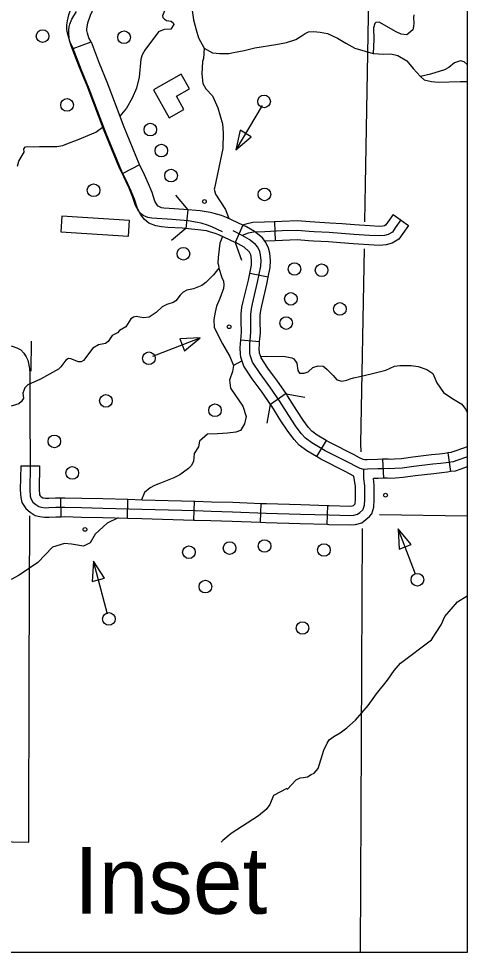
# Model space of a CAD drawing. Extents: x 1382482 to 1385815, y 1168351 to 1170484.
# Drawn here: x 1384797.7 to 1384939.9, y 1168702.4 to 1168998.2 of the extents above; entities that cross this region are included whole.
import ezdxf

# ---------------------------------------------------------------- set-up
doc = ezdxf.new("R2010")
doc.units = 0
for name, color, linetype in [('32', 7, 'Continuous'), ('35', 7, 'Continuous'), ('38', 7, 'Continuous'), ('45', 7, 'Continuous'), ('5', 7, 'Continuous'), ('57', 7, 'Continuous'), ('6', 7, 'Continuous'), ('Default', 7, 'Continuous'), ('R_No Plot', 7, 'Continuous')]:
    doc.layers.add(name, color=color, linetype=linetype)

msp = doc.modelspace()

# ---------------------------------------------------------------- linework, layer by layer
at = {"layer": '32'}
for p, q in [((1384876.81, 1168916.28), (1384870.93, 1168917.47)), ((1384874.06, 1168895.8), (1384868.08, 1168896.31)), ((1384882.46, 1168879.36), (1384877.53, 1168875.94)), ((1384895.17, 1168864.55), (1384892.09, 1168859.4)), ((1384913.04, 1168858.57), (1384913.3, 1168852.57)), ((1384933.73, 1168860.59), (1384934.57, 1168854.65)), ((1384798.36, 1168856.54), (1384804.35, 1168856.44)), ((1384811.16, 1168840.37), (1384811.08, 1168846.37)), ((1384832.15, 1168839.89), (1384832.32, 1168845.89)), ((1384853.26, 1168839.29), (1384853.43, 1168845.29)), ((1384874.33, 1168838.61), (1384874.57, 1168844.6)), ((1384895.47, 1168837.96), (1384895.65, 1168843.96))]:
    msp.add_line(p, q, dxfattribs=at)
for points in [[(1384876.81, 1168916.28), (1384877.44, 1168919.37), (1384877.54, 1168921.58), (1384877.33, 1168923.92), (1384876.9, 1168925.45), (1384876.04, 1168927.3), (1384874.93, 1168928.74), (1384872.96, 1168930.36), (1384872.42, 1168930.76), (1384869.95, 1168932.16), (1384868.74, 1168932.75)], [(1384939.88, 1168859.32), (1384939.35, 1168859.13), (1384936.85, 1168858.24), (1384935.35, 1168857.79), (1384933.16, 1168857.48), (1384931.42, 1168857.25), (1384928.9, 1168856.98), (1384922.98, 1168856.28), (1384919.28, 1168855.75), (1384916.95, 1168855.62), (1384915.36, 1168855.52), (1384914.76, 1168855.6), (1384913.4, 1168855.58), (1384911.48, 1168855.5), (1384908.27, 1168855.39), (1384907.11, 1168855.35), (1384905.93, 1168855.62), (1384904.41, 1168856.34), (1384902.61, 1168857.31), (1384894.87, 1168861.24), (1384890.66, 1168863.76), (1384888.63, 1168865.24), (1384887.27, 1168866.77), (1384885.41, 1168869.21), (1384883.31, 1168872.39), (1384880.4, 1168877.08), (1384877.3, 1168881.54), (1384874.2, 1168885.75), (1384871.81, 1168889.38), (1384871.48, 1168890.33), (1384871.03, 1168891.57), (1384870.98, 1168892.15), (1384870.94, 1168893.72), (1384870.98, 1168895.08), (1384871.29, 1168898.7), (1384871.23, 1168902.34), (1384871.23, 1168904.4), (1384871.44, 1168906.25), (1384871.81, 1168907.86), (1384873.42, 1168914.66), (1384874.45, 1168919.74), (1384874.54, 1168921.52), (1384874.37, 1168923.37), (1384874.08, 1168924.41), (1384873.46, 1168925.73), (1384872.76, 1168926.64), (1384871.11, 1168928), (1384870.78, 1168928.25), (1384868.56, 1168929.5), (1384865.7, 1168930.9)], [(1384870.93, 1168917.47), (1384871.47, 1168920.11), (1384871.53, 1168921.45), (1384871.41, 1168922.83), (1384871.26, 1168923.36), (1384870.89, 1168924.16), (1384870.59, 1168924.54), (1384869.25, 1168925.64), (1384869.13, 1168925.73), (1384866.33, 1168927.32)], [(1384868.08, 1168896.31), (1384868.29, 1168898.8), (1384868.23, 1168902.31), (1384868.23, 1168904.57), (1384868.47, 1168906.75), (1384868.89, 1168908.54), (1384870.49, 1168915.3), (1384870.93, 1168917.47)], [(1384874.06, 1168895.8), (1384874.3, 1168898.59), (1384874.23, 1168902.37), (1384874.23, 1168904.24), (1384874.4, 1168905.75), (1384874.73, 1168907.18), (1384876.35, 1168914.01), (1384876.81, 1168916.28)], [(1384877.53, 1168875.94), (1384874.86, 1168879.79), (1384871.74, 1168884.03), (1384869.1, 1168888.05), (1384868.65, 1168889.32), (1384868.06, 1168890.94), (1384867.99, 1168892), (1384867.94, 1168893.73), (1384867.99, 1168895.26), (1384868.08, 1168896.31)], [(1384882.46, 1168879.36), (1384879.74, 1168883.28), (1384876.67, 1168887.46), (1384874.52, 1168890.72), (1384874.31, 1168891.34), (1384873.99, 1168892.21), (1384873.98, 1168892.3), (1384873.94, 1168893.71), (1384873.98, 1168894.91), (1384874.06, 1168895.8)], [(1384895.17, 1168864.55), (1384892.32, 1168866.26), (1384890.66, 1168867.48), (1384889.59, 1168868.68), (1384887.86, 1168870.95), (1384885.83, 1168874.01), (1384882.91, 1168878.72), (1384882.46, 1168879.36)], [(1384892.09, 1168859.4), (1384889, 1168861.26), (1384886.6, 1168863.01), (1384884.96, 1168864.86), (1384882.97, 1168867.47), (1384880.78, 1168870.77), (1384877.89, 1168875.43), (1384877.53, 1168875.94)], [(1384913.04, 1168858.57), (1384911.37, 1168858.5), (1384908.16, 1168858.39), (1384907.4, 1168858.36), (1384906.92, 1168858.47), (1384905.76, 1168859.02), (1384904, 1168859.97), (1384896.32, 1168863.87), (1384895.17, 1168864.55)], [(1384939.88, 1168862.51), (1384938.34, 1168861.96), (1384935.92, 1168861.09), (1384934.7, 1168860.73), (1384933.73, 1168860.59)], [(1384903.95, 1168853.18), (1384901.22, 1168854.66), (1384893.42, 1168858.61), (1384892.09, 1168859.4)], [(1384933.73, 1168860.59), (1384932.75, 1168860.45), (1384931.07, 1168860.23), (1384928.57, 1168859.97), (1384922.58, 1168859.26), (1384918.99, 1168858.73), (1384916.77, 1168858.62), (1384915.47, 1168858.53), (1384914.94, 1168858.6), (1384913.31, 1168858.58), (1384913.04, 1168858.57)], [(1384798.36, 1168856.54), (1384798.22, 1168848.88), (1384798.36, 1168846.44), (1384798.74, 1168844.92), (1384799.96, 1168842.96), (1384801.33, 1168841.83), (1384802.94, 1168840.78), (1384804.45, 1168840.44), (1384805.89, 1168840.22), (1384807.42, 1168840.27), (1384809.52, 1168840.35), (1384811.16, 1168840.37)], [(1384801.36, 1168856.49), (1384801.22, 1168848.94), (1384801.34, 1168846.89), (1384801.54, 1168846.1), (1384802.25, 1168844.96), (1384803.11, 1168844.25), (1384804.13, 1168843.58), (1384805, 1168843.39), (1384806.06, 1168843.23), (1384807.32, 1168843.27), (1384809.44, 1168843.35), (1384812.36, 1168843.39), (1384817.67, 1168843.27), (1384824.36, 1168843.11), (1384836.79, 1168842.76), (1384853.59, 1168842.29), (1384858.71, 1168842.13), (1384865.45, 1168841.97), (1384876.11, 1168841.54), (1384887.05, 1168841.22), (1384896.05, 1168840.95), (1384902.83, 1168840.75), (1384903.9, 1168840.87), (1384905.11, 1168841.18), (1384905.82, 1168841.74), (1384906.73, 1168842.56), (1384906.92, 1168842.8), (1384907.32, 1168843.98), (1384907.4, 1168845.79), (1384907.4, 1168848.31), (1384907.4, 1168850.16), (1384907.08, 1168852.44), (1384907.08, 1168853.86), (1384907.11, 1168855.35)], [(1384804.35, 1168856.44), (1384804.22, 1168849), (1384804.32, 1168847.34), (1384804.33, 1168847.29), (1384804.53, 1168846.97), (1384804.89, 1168846.68), (1384805.32, 1168846.39), (1384805.55, 1168846.34), (1384806.24, 1168846.24), (1384807.22, 1168846.27), (1384809.37, 1168846.35), (1384811.08, 1168846.37)], [(1384939.88, 1168856.14), (1384937.79, 1168855.39), (1384935.99, 1168854.85), (1384934.57, 1168854.65)], [(1384895.65, 1168843.96), (1384896.14, 1168843.95), (1384902.71, 1168843.76), (1384903.35, 1168843.83), (1384903.76, 1168843.93), (1384903.89, 1168844.03), (1384904.3, 1168844.41), (1384904.34, 1168844.53), (1384904.4, 1168845.85), (1384904.4, 1168848.31), (1384904.4, 1168849.95), (1384903.95, 1168853.18)], [(1384913.3, 1168852.57), (1384911.59, 1168852.5), (1384910.11, 1168852.45)], [(1384934.57, 1168854.65), (1384933.56, 1168854.51), (1384931.78, 1168854.27), (1384929.24, 1168854), (1384923.37, 1168853.31), (1384919.58, 1168852.76), (1384917.13, 1168852.63), (1384915.25, 1168852.5), (1384914.58, 1168852.6), (1384913.49, 1168852.58), (1384913.3, 1168852.57)], [(1384895.47, 1168837.96), (1384895.97, 1168837.95), (1384902.96, 1168837.75), (1384904.44, 1168837.91), (1384906.47, 1168838.43), (1384907.76, 1168839.44), (1384908.9, 1168840.48), (1384909.59, 1168841.31), (1384910.3, 1168843.43), (1384910.4, 1168845.72), (1384910.4, 1168848.31), (1384910.4, 1168850.36), (1384910.11, 1168852.45)], [(1384811.08, 1168846.37), (1384812.37, 1168846.39), (1384817.74, 1168846.27), (1384824.43, 1168846.11), (1384832.32, 1168845.89)], [(1384832.32, 1168845.89), (1384836.88, 1168845.76), (1384853.43, 1168845.29)], [(1384853.43, 1168845.29), (1384853.68, 1168845.28), (1384858.79, 1168845.13), (1384865.54, 1168844.97), (1384874.57, 1168844.6)], [(1384874.57, 1168844.6), (1384876.21, 1168844.54), (1384887.13, 1168844.22), (1384895.65, 1168843.96)], [(1384811.16, 1168840.37), (1384812.34, 1168840.39), (1384817.6, 1168840.27), (1384824.28, 1168840.11), (1384832.15, 1168839.89)], [(1384832.15, 1168839.89), (1384836.71, 1168839.76), (1384853.26, 1168839.29)], [(1384853.26, 1168839.29), (1384853.51, 1168839.29), (1384858.63, 1168839.13), (1384865.35, 1168838.97), (1384874.33, 1168838.61)], [(1384874.33, 1168838.61), (1384876, 1168838.54), (1384886.96, 1168838.22), (1384895.47, 1168837.96)]]:
    msp.add_lwpolyline(points, dxfattribs=at)
at = {"layer": '35'}
for points in [[(1384835.69, 1169026.55), (1384836.09, 1169023.36), (1384836.89, 1169020.7), (1384838.35, 1169018.45), (1384845.77, 1169011.14), (1384850.52, 1169007.38), (1384852.13, 1169004.43), (1384853.07, 1168997.75), (1384853.93, 1168994.6), (1384854.68, 1168992.12), (1384856.51, 1168988.77)], [(1384845.77, 1169011.14), (1384845.29, 1169006.66), (1384844.66, 1169003.27), (1384843.9, 1169000.69), (1384843.32, 1168999.09), (1384843.44, 1168998.57), (1384843.92, 1168997.98), (1384844.6, 1168997.62), (1384846.04, 1168997.39), (1384846.68, 1168996.88), (1384846.92, 1168996.32), (1384845.89, 1168994.87), (1384843.78, 1168994.78), (1384842.03, 1168994), (1384837.65, 1168988.18), (1384836.86, 1168986.73), (1384836.43, 1168985.33), (1384835.87, 1168979.68), (1384835, 1168976.14), (1384833.69, 1168973.02), (1384831.83, 1168969.77), (1384829.73, 1168967.27)], [(1384922.89, 1168999.39), (1384922.81, 1168998.41), (1384922.98, 1168996.73), (1384922.78, 1168995.69), (1384922.61, 1168994.58), (1384920.71, 1168993.02), (1384918.87, 1168993.24), (1384917.34, 1168994), (1384911.91, 1168997.03), (1384910.91, 1168996.92), (1384910.55, 1168996.58), (1384910.2, 1168995.29), (1384910.24, 1168991.52), (1384910.04, 1168987.09)], [(1384856.51, 1168988.77), (1384859.1, 1168987.31), (1384861.44, 1168987.1), (1384864.28, 1168987.17), (1384865.82, 1168987.42), (1384869.17, 1168988.09), (1384872.58, 1168988.87), (1384879.17, 1168989.93), (1384882.58, 1168990.57), (1384885.49, 1168991.57), (1384887.26, 1168992.63), (1384888.46, 1168993.46), (1384889.52, 1168993.96), (1384891.16, 1168994.1), (1384893.25, 1168993.85), (1384895.59, 1168993.44), (1384898.76, 1168991.94), (1384901.37, 1168990.42)], [(1384856.51, 1168988.77), (1384856.24, 1168985.59), (1384855.96, 1168984.55), (1384855.71, 1168980.71), (1384856.05, 1168977.59), (1384857.02, 1168975.92), (1384859.14, 1168973.73), (1384860.8, 1168969.87), (1384862.31, 1168964.8), (1384862.56, 1168961.96), (1384862.36, 1168957.06), (1384859.72, 1168944.44), (1384859.68, 1168944.15), (1384860.07, 1168942.58), (1384863.3, 1168937.7), (1384864.35, 1168934.8)], [(1384901.37, 1168990.42), (1384904.27, 1168988.82), (1384910.04, 1168987.09), (1384913.38, 1168986.96), (1384915.61, 1168987.01), (1384917.81, 1168986.46), (1384920.76, 1168984.79), (1384922.77, 1168982.42), (1384925.03, 1168979.81), (1384926.25, 1168978.79), (1384928.55, 1168978.22), (1384930.67, 1168978.07), (1384937.74, 1168978.3), (1384939.88, 1168978.21)], [(1384939.88, 1168983.62), (1384938.88, 1168984.45), (1384937.72, 1168984.76), (1384935.85, 1168984.15), (1384933.99, 1168982.74), (1384932.6, 1168981.97), (1384928.22, 1168980.62), (1384925.03, 1168979.81)], [(1384797.34, 1168951.4), (1384797.73, 1168953.05), (1384798.83, 1168954.78), (1384799.46, 1168955.89), (1384799.38, 1168956.91), (1384799.85, 1168957.54), (1384800.56, 1168957.62), (1384802.37, 1168957.54), (1384804.34, 1168957.62), (1384805.99, 1168957.62), (1384808.35, 1168957.7), (1384809.77, 1168957.7), (1384811.66, 1168958.01), (1384813.54, 1168958.72), (1384816.38, 1168959.82), (1384822.12, 1168962.18), (1384824.57, 1168963.95)], [(1384862.33, 1168929.1), (1384861.48, 1168927.08), (1384860.91, 1168922.49), (1384860.78, 1168920.7), (1384861, 1168920.02), (1384861.15, 1168919.16), (1384862.04, 1168916.21), (1384862.59, 1168915.03), (1384862.77, 1168913.88), (1384862.59, 1168912.67), (1384861.49, 1168909.52), (1384860.41, 1168907.03), (1384860.02, 1168905.22), (1384859.58, 1168902.9), (1384859.62, 1168900.34), (1384862.27, 1168895.15), (1384864.61, 1168891.09), (1384865.76, 1168888.28), (1384865.52, 1168886.39), (1384864.5, 1168883.64), (1384864.8, 1168881.08), (1384868.75, 1168875.37), (1384869.85, 1168872.07), (1384869.3, 1168869.78), (1384868.04, 1168867.66), (1384866.51, 1168867.19), (1384863.84, 1168866.81), (1384860.69, 1168866.59), (1384857.58, 1168866.48), (1384854.98, 1168864.35), (1384854.7, 1168862.51), (1384853.33, 1168860.42), (1384853.15, 1168857.85), (1384852.4, 1168856.53), (1384851.48, 1168855.63), (1384848.74, 1168853.66), (1384846.91, 1168852.66), (1384842.62, 1168850.99)], [(1384861.15, 1168919.16), (1384859.5, 1168916.96), (1384857, 1168914.55), (1384855.77, 1168913.62), (1384853.15, 1168912.52), (1384850.96, 1168912.1), (1384849.85, 1168911.5), (1384848.9, 1168910.61), (1384847.51, 1168908.8), (1384846.68, 1168908.28), (1384844.69, 1168907.62), (1384843.18, 1168906.89), (1384841.28, 1168905.08), (1384839.06, 1168903.58), (1384837.22, 1168903.37), (1384834.99, 1168903.8), (1384834.07, 1168903.63), (1384833.28, 1168903.06), (1384831.62, 1168900.53), (1384829.71, 1168899.32), (1384829.08, 1168898.6), (1384827.37, 1168897.78), (1384826.03, 1168895.9), (1384825.24, 1168895.25), (1384823.01, 1168894.79), (1384821.26, 1168893.78), (1384818.29, 1168889.84), (1384817.5, 1168889.48), (1384816.62, 1168889.47), (1384814.19, 1168890.41), (1384813.47, 1168890.45), (1384812.63, 1168890), (1384811.05, 1168887.83), (1384810.34, 1168887.15), (1384804.58, 1168883.99), (1384800.59, 1168882.15)], [(1384874.4, 1168891.09), (1384876.4, 1168891.26), (1384882.21, 1168891.18), (1384884.25, 1168890.73), (1384884.92, 1168890.35), (1384885.9, 1168889.07), (1384886.13, 1168886.73), (1384886.66, 1168885.9), (1384887.34, 1168885.83), (1384888.17, 1168885.9), (1384889.45, 1168886.28), (1384890.96, 1168887.64), (1384892.62, 1168888.14), (1384894.21, 1168888.07), (1384894.58, 1168887.79), (1384895.48, 1168886.96), (1384897.37, 1168885.07), (1384898.5, 1168883.79), (1384900.16, 1168883.34), (1384901.75, 1168883.64), (1384902.73, 1168884.09), (1384903.86, 1168884.32), (1384905.82, 1168884.77), (1384909.82, 1168885.75), (1384914.04, 1168886.81), (1384916.76, 1168888.02), (1384918.49, 1168888.24), (1384922.04, 1168888.24), (1384924.3, 1168887.94), (1384927.02, 1168886.96), (1384928.98, 1168885.75), (1384930.26, 1168882.81), (1384932.37, 1168879.72), (1384934.94, 1168877.9), (1384938.1, 1168876.02), (1384939.28, 1168874.43), (1384939.88, 1168873.47)], [(1384868.49, 1168889.78), (1384865.76, 1168888.28)], [(1384800.59, 1168882.15), (1384799.68, 1168881.17), (1384799.03, 1168879.54), (1384799.29, 1168877.91), (1384798.64, 1168876.86), (1384797.72, 1168876.14), (1384795.31, 1168875.43)], [(1384842.62, 1168850.99), (1384840.75, 1168850.3), (1384839.4, 1168849.49), (1384837.61, 1168848.08), (1384836.62, 1168845.76)], [(1384829.27, 1168839.97), (1384825.75, 1168838.34), (1384821.97, 1168834.8), (1384820.32, 1168832.12), (1384818.21, 1168831.02), (1384814.5, 1168831.65), (1384812.24, 1168831.9), (1384808.46, 1168830.68), (1384803.8, 1168825.9), (1384797.88, 1168821.89), (1384795.37, 1168820.47)], [(1384882.77, 1168753.92), (1384885.68, 1168757.01), (1384886.89, 1168757.69), (1384888.02, 1168757.76), (1384889.2, 1168758), (1384890.38, 1168758.65), (1384891.32, 1168759.13), (1384892.63, 1168760.59), (1384894.44, 1168766.4), (1384895.5, 1168768.59), (1384896.1, 1168769.65), (1384897.61, 1168770.78), (1384899.57, 1168771.91), (1384901.68, 1168773.5), (1384904.44, 1168775.87), (1384908.51, 1168780.55), (1384911.07, 1168784.23), (1384914.54, 1168788.64), (1384916.69, 1168791.66), (1384918.66, 1168793.93), (1384928.54, 1168801.32), (1384930.05, 1168803.66), (1384931.63, 1168806.07), (1384932.79, 1168808.8), (1384936.8, 1168813.45), (1384939.88, 1168815.3)], [(1384882.67, 1168754.25), (1384878.43, 1168752.03), (1384877.34, 1168749.22), (1384876.12, 1168747.61), (1384873.75, 1168745.59), (1384865.08, 1168740.06), (1384862.39, 1168737.8), (1384861.93, 1168737.28)]]:
    msp.add_lwpolyline(points, dxfattribs=at)
at = {"layer": '38'}
for points in [[(1384847.44, 1168942.25), (1384851.27, 1168937.63)], [(1384850.72, 1168931.66), (1384846.1, 1168927.83)], [(1384866.31, 1168927.27), (1384868.31, 1168921.61)], [(1384882.47, 1168879.35), (1384888.37, 1168878.26)], [(1384876.43, 1168870.06), (1384877.52, 1168875.95)]]:
    msp.add_lwpolyline(points, dxfattribs=at)
at = {"layer": '45'}
for p, q in [((1384916.36, 1168936.13), (1384921.26, 1168932.67)), ((1384878.76, 1168933.82), (1384879.03, 1168927.82))]:
    msp.add_line(p, q, dxfattribs=at)
for points in [[(1384916.36, 1168936.13), (1384914.55, 1168933.57), (1384914.03, 1168932.82), (1384913.61, 1168932.58), (1384913.06, 1168932.4), (1384912.02, 1168932.33), (1384909.03, 1168932.5), (1384904.15, 1168932.82), (1384900.21, 1168933.12)], [(1384918.81, 1168934.4), (1384917, 1168931.85), (1384916.12, 1168930.57), (1384914.84, 1168929.82), (1384913.63, 1168929.43), (1384912.04, 1168929.33), (1384908.85, 1168929.5), (1384903.94, 1168929.82), (1384896.13, 1168930.43), (1384891.35, 1168930.67), (1384889.73, 1168930.78), (1384886.04, 1168931.06), (1384881.22, 1168930.92), (1384875.68, 1168930.67), (1384872.24, 1168930.57), (1384870.47, 1168930.18), (1384868.56, 1168929.5)], [(1384878.76, 1168933.82), (1384875.57, 1168933.67), (1384871.87, 1168933.56), (1384869.65, 1168933.07), (1384868.74, 1168932.75)], [(1384900.21, 1168933.12), (1384896.33, 1168933.42), (1384891.52, 1168933.67), (1384889.94, 1168933.77), (1384886.11, 1168934.07), (1384881.1, 1168933.92), (1384878.76, 1168933.82)], [(1384921.26, 1168932.67), (1384919.46, 1168930.12), (1384918.2, 1168928.31), (1384916.07, 1168927.07), (1384914.2, 1168926.46), (1384912.05, 1168926.32), (1384908.67, 1168926.51), (1384903.72, 1168926.83), (1384899.74, 1168927.14)], [(1384879.03, 1168927.82), (1384875.75, 1168927.67)], [(1384899.74, 1168927.14), (1384895.94, 1168927.43), (1384891.17, 1168927.68), (1384889.51, 1168927.79), (1384885.97, 1168928.06), (1384881.33, 1168927.92), (1384879.03, 1168927.82)]]:
    msp.add_lwpolyline(points, dxfattribs=at)
at = {"layer": '5'}
for points in [[(1384909.19, 1169040.45), (1384907.53, 1168945.64), (1384907.32, 1168933.79)], [(1384907.16, 1168925.29), (1384906.03, 1168863.61), (1384906.1, 1168860.9)], [(1384939.88, 1168840.58), (1384912.08, 1168841.02)], [(1384906.55, 1168836.66), (1384905.95, 1168702.36)]]:
    msp.add_lwpolyline(points, dxfattribs=at)
at = {"layer": '57'}
for p, q in [((1384811.35, 1168935.6), (1384811.03, 1168930.61)), ((1384832.8, 1168934.22), (1384811.35, 1168935.6)), ((1384832.48, 1168929.23), (1384832.8, 1168934.22)), ((1384811.03, 1168930.61), (1384832.48, 1168929.23))]:
    msp.add_line(p, q, dxfattribs=at)
at = {"layer": '6'}
for points in [[(1384801.67, 1168886.52), (1384801.77, 1168896.01)], [(1384641.36, 1168833.44), (1384648.72, 1168818.32), (1384660.74, 1168791.71), (1384671.75, 1168768.87), (1384676.42, 1168757.19), (1384679.74, 1168760.63), (1384697.07, 1168764.33), (1384697.09, 1168792.43), (1384748.51, 1168791.38), (1384748.43, 1168738.33), (1384800.97, 1168737.3), (1384801.09, 1168790.31), (1384801.21, 1168840.6)]]:
    msp.add_lwpolyline(points, dxfattribs=at)
at = {"layer": 'Default'}
for p, q in [((1384815.03, 1168988.69), (1384820.64, 1168990.82)), ((1384815.03, 1168988.69), (1384815.03, 1168988.69)), ((1384836.04, 1168951.83), (1384830.68, 1168949.13)), ((1384851.27, 1168937.63), (1384850.72, 1168931.66)), ((1384868.74, 1168932.75), (1384866.31, 1168927.27))]:
    msp.add_line(p, q, dxfattribs=at)
for points in [[(1384815.05, 1168988.7), (1384814.99, 1168988.81), (1384814.02, 1168990.7), (1384813.28, 1168993.14), (1384813.01, 1168994.76), (1384812.96, 1168996.17), (1384813.15, 1168997.45), (1384813.59, 1168999.42), (1384814.69, 1169002.36), (1384815.9, 1169005.13), (1384816.41, 1169006.23), (1384816.42, 1169006.43), (1384816.36, 1169007.7)], [(1384820.65, 1168990.8), (1384819.97, 1168992.07), (1384819.48, 1168993.59), (1384819.33, 1168994.45), (1384819.31, 1168994.94), (1384819.38, 1168995.46), (1384819.65, 1168996.81), (1384820.52, 1168999.23), (1384821.6, 1169001.8), (1384822.53, 1169003.9), (1384822.59, 1169005.55), (1384822.54, 1169006.36)], [(1384862.28, 1168930.67), (1384858.92, 1168932.17), (1384857.54, 1168932.76), (1384855.5, 1168933.35), (1384854.36, 1168933.62), (1384851.45, 1168934.06), (1384846.37, 1168934.53), (1384839.9, 1168934.92), (1384838.64, 1168935.16), (1384837.14, 1168935.79), (1384836.32, 1168936.46), (1384835.53, 1168937.44), (1384834.7, 1168938.97), (1384833.8, 1168941.81), (1384832.74, 1168944.44), (1384831.04, 1168948.07), (1384829.67, 1168950.8), (1384824.79, 1168962.6), (1384819.4, 1168976.83), (1384817, 1168982.73), (1384814.4, 1168989.58), (1384813.85, 1168991.27), (1384813.58, 1168993.33), (1384813.58, 1168994.59), (1384813.69, 1168995.53), (1384813.97, 1168996.4), (1384814.6, 1168997.97), (1384816.02, 1169000.45)], [(1384822.66, 1168969), (1384820.02, 1168975.96), (1384817.62, 1168981.86), (1384815.03, 1168988.69)], [(1384820.64, 1168990.82), (1384823.21, 1168984.05), (1384825.61, 1168978.15), (1384828.27, 1168971.13)], [(1384828.27, 1168971.13), (1384830.99, 1168963.94), (1384835.81, 1168952.27), (1384836.04, 1168951.83)], [(1384830.68, 1168949.13), (1384830.35, 1168949.77), (1384825.42, 1168961.73), (1384822.66, 1168969)], [(1384874.89, 1168970.66), (1384866.49, 1168956.56)], [(1384845.38, 1168938.03), (1384843.68, 1168938.13), (1384842.92, 1168938.27), (1384842.11, 1168938.61), (1384841.87, 1168938.81), (1384841.46, 1168939.33), (1384840.89, 1168940.38), (1384840.04, 1168943.05), (1384838.9, 1168945.87), (1384837.16, 1168949.6), (1384836.04, 1168951.83)], [(1384845.02, 1168932.04), (1384842.94, 1168932.17), (1384841.18, 1168932.5), (1384839, 1168933.42), (1384837.59, 1168934.56), (1384836.43, 1168936.01), (1384835.35, 1168938.03), (1384834.39, 1168941.02), (1384833.4, 1168943.48), (1384831.76, 1168946.98), (1384830.68, 1168949.13)], [(1384868.74, 1168932.75), (1384863.54, 1168935.14), (1384861.97, 1168935.82), (1384859.68, 1168936.48), (1384858.35, 1168936.8), (1384855.22, 1168937.26), (1384850.02, 1168937.75), (1384845.38, 1168938.03)], [(1384866.31, 1168927.27), (1384861.14, 1168929.65), (1384859.95, 1168930.15), (1384858.15, 1168930.67), (1384857.2, 1168930.9), (1384854.5, 1168931.3), (1384849.56, 1168931.76), (1384845.02, 1168932.04)], [(1384840.23, 1168891.24), (1384855.23, 1168897.07)], [(1384749.05, 1168896.25), (1384783.7, 1168895.16), (1384791.96, 1168894.93), (1384794, 1168894.85), (1384795.7, 1168894.42), (1384797.15, 1168893.87), (1384798.37, 1168893.2), (1384799.35, 1168892.17), (1384800.11, 1168890.98), (1384800.59, 1168889.94), (1384801.12, 1168887.3), (1384801.2, 1168885.96)], [(1384801.2, 1168885.96), (1384801.22, 1168873.51), (1384801.36, 1168856.49)], [(1384923.44, 1168822.18), (1384917.94, 1168836.51)], [(1384825.81, 1168809.48), (1384821.4, 1168826.28)]]:
    msp.add_lwpolyline(points, dxfattribs=at)
for points in [[(1384840.4, 1168975.6), (1384845.38, 1168966.74), (1384850.06, 1168969.37), (1384847.7, 1168973.56), (1384851.88, 1168975.92), (1384849.25, 1168980.58)], [(1384871.38, 1168960.77), (1384867.87, 1168962.86), (1384866.49, 1168956.56)], [(1384848.78, 1168896.75), (1384850.26, 1168892.95), (1384855.23, 1168897.07)], [(1384918.23, 1168830.06), (1384922.04, 1168831.53), (1384917.94, 1168836.51)], [(1384820.98, 1168819.84), (1384824.93, 1168820.88), (1384821.4, 1168826.28)]]:
    msp.add_lwpolyline(points, close=True, dxfattribs=at)
for centre, radius in [((1384805.29, 1168992.63), 2), ((1384831.11, 1168992.26), 2), ((1384875.49, 1168971.93), 2), ((1384813.06, 1168970.82), 2), ((1384839.43, 1168963.03), 2), ((1384842.92, 1168956.38), 2), ((1384846, 1168948.44), 2), ((1384821.47, 1168943.8), 2), ((1384875.6, 1168942.47), 2), ((1384856.57, 1168940.25), 0.6), ((1384849.93, 1168923.67), 2), ((1384885.12, 1168918.85), 2), ((1384893.71, 1168918.47), 2), ((1384883.96, 1168909.39), 2), ((1384899.49, 1168906.2), 2), ((1384882.48, 1168901.71), 2), ((1384864.4, 1168900.55), 0.6), ((1384838.97, 1168890.57), 2), ((1384825.37, 1168877.08), 2), ((1384859.92, 1168874.09), 2), ((1384809.02, 1168864.22), 2), ((1384814.7, 1168854.23), 2), ((1384913.95, 1168847.21), 0.6), ((1384818.72, 1168836.35), 0.6), ((1384864.54, 1168830.42), 2), ((1384875.62, 1168831.09), 2), ((1384851.65, 1168829.13), 2), ((1384894.43, 1168829.83), 2), ((1384856.9, 1168818.22), 2), ((1384924.05, 1168820.41), 2), ((1384826.29, 1168807.98), 2), ((1384887.65, 1168805.11), 2)]:
    msp.add_circle(centre, radius, dxfattribs=at)
at = {"layer": 'R_No Plot'}
msp.add_lwpolyline([(1383432.46, 1169579.7), (1384939.88, 1169579.7), (1384939.88, 1168702.36), (1383432.46, 1168702.36)], close=True, dxfattribs=at)

# ---------------------------------------------------------------- texts
at = {"layer": 'Default'}
msp.add_text('Inset', height=21.12, dxfattribs=at).set_placement((1384815.26, 1168714.59))

doc.saveas('drawing.dxf')
